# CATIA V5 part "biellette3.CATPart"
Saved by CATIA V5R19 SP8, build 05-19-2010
Part number: biellette3
Bounding box of the stored display mesh (mm): x -2.149 to 7.851, y 255.203 to 325.788, z 65.318 to 91.058
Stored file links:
  G:\EU_thinkMotion\CFAO_2010\MMS_groupe3\MMS_groupe3\A reprendre\amenand\amenand\biellette3.CATPart
  F:\thinkmotion CFAO v12.1\essuie_glace.CATProduct
  G:\EU_thinkMotion\CFAO_2010\MMS_groupe3\MMS_groupe3\A reprendre\amenand\amenand\pignon.CATPart
  G:\EU_thinkMotion\CFAO_2010\MMS_groupe3\MMS_groupe3\A reprendre\amenand\amenand\balai.CATPart
  G:\EU_thinkMotion\CFAO_2010\MMS_groupe3\MMS_groupe3\A reprendre\amenand\amenand\coulisseau.CATPart
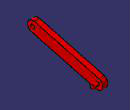
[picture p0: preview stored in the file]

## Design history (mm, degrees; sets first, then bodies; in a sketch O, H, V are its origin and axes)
Set1
  DatumCurve1: linked copy from another document
  Plane1: linked copy from another document
  Plane2: linked copy from another document
  Line1: linked copy from another document
  Point1: linked copy from another document
Body1 (main body)
  Sketch1 on Plane2, origin (2.8512, 303.534, 86.2258), H (0, 1, 0), V (0, 0, 1)
    circle A1 centre (17.4193, -16.0735) radius 2
    reference projected circle E1 centre (17.4193, -16.0735) radius 2 from edge of DatumCurve1
    coincidence: A1 E1
  Pad1: profile Sketch1, direction (1, 0, 0), up to Plane1
  Sketch2 on Plane2, origin (2.8512, 303.534, 86.2258), H (0, 1, 0), V (0, 0, 1)
    arc A1 centre (17.4193, -16.0735) radius 5 from (16.1437, -20.908) to (18.6948, -11.2389) ccw
    reference projected circle E1 centre (17.4193, -16.0735) radius 2 from edge of DatumCurve1
    arc A2 centre (-43.4963, -0.0019) radius 5 from (-42.2208, 4.8327) to (-44.7718, -4.8365) ccw
    circle A3 centre (-43.4963, -0.0019) radius 2
    point P3 (-43.4963, -0.0019)
    reference projected point E2 (-43.4963, -0.0019) from Point1
    line L1 (18.6948, -11.2389) -> (-42.2208, 4.8327)
    line L2 (16.1437, -20.908) -> (-44.7718, -4.8365)
    reference projected line E3 (40.2868, -22.1067) -> (-51.57, 2.1282) from Line1
    radius A1 = 5
    radius A3 = 2
    radius A2 = 5
    concentricity: A1 E1, A3 A2
    coincidence: P3 E2
    parallelism: L2 L1, L1 E3
    tangency: L1 A1, L2 A2
  Pad2: profile Sketch2, direction (-1, 0, 0), length 5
